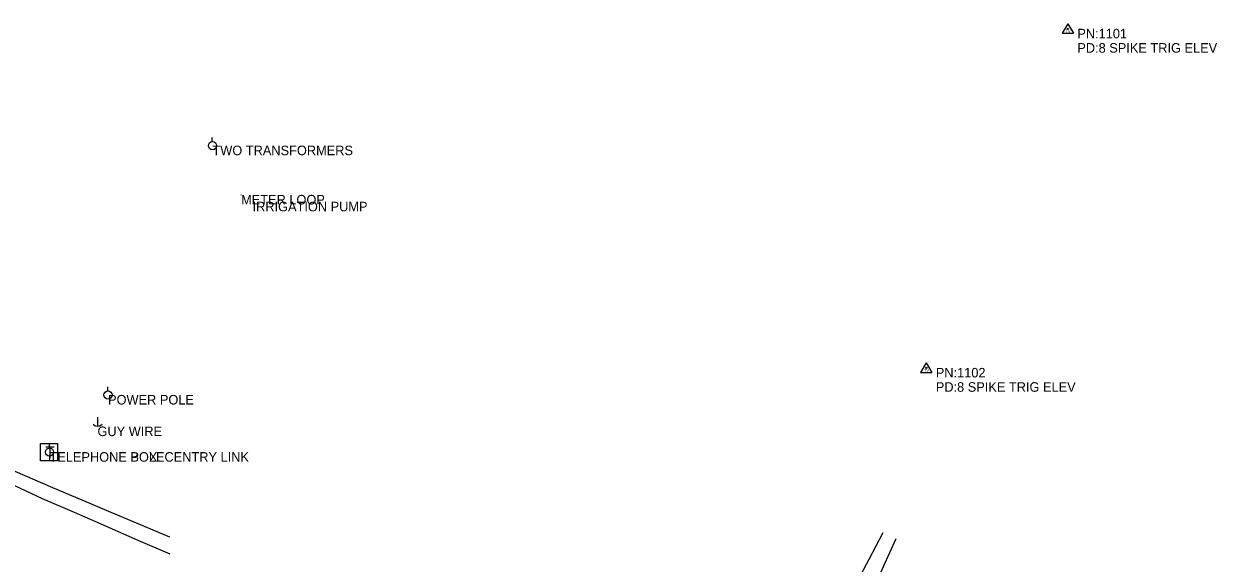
# Model space of a CAD drawing. Extents: x 1411444 to 1458157, y 300965 to 327300.
# Drawn here: x 1454655 to 1455280, y 302865 to 303147 of the extents above; entities that cross this region are included whole.
import ezdxf

# ---------------------------------------------------------------- set-up
doc = ezdxf.new("R2010")
doc.units = 0
for name, color, linetype in [('S_DITCHLINE', 7, 'Continuous'), ('S_GRAVEL_ROAD', 7, 'Continuous'), ('S_MISC_STRUCTURES_ANNOT', 7, 'Continuous'), ('S_MSC_PT_SYM', 7, 'Continuous'), ('S_SECONDARY_CTL', 7, 'Continuous'), ('S_SECONDARY_CTL_ANNOT', 7, 'Continuous'), ('S_TELEPHONE_UTILITIES', 7, 'Continuous'), ('S_TELEPHONE_UTILITIES_ANNOT', 7, 'Continuous'), ('S_UTILITY_POLE', 7, 'Continuous'), ('S_UTILITY_POLE_ANNOT', 7, 'Continuous')]:
    doc.layers.add(name, color=color, linetype=linetype)

msp = doc.modelspace()

# ---------------------------------------------------------------- linework, layer by layer
at = {"layer": 'S_DITCHLINE'}
for points in [[(1454731.72, 302869.5), (1454715.03, 302876.77), (1454698.33, 302884.04), (1454681.64, 302891.31), (1454664.94, 302898.58), (1454644.54, 302908.11), (1454624.14, 302917.64)], [(1454630.76, 302921.5), (1454650.43, 302913.01), (1454670.1, 302904.51), (1454685.4, 302898.04), (1454700.71, 302891.57), (1454716.01, 302885.1), (1454731.32, 302878.63)]]:
    msp.add_lwpolyline(points, dxfattribs=at)
at = {"layer": 'S_GRAVEL_ROAD'}
for points in [[(1455052.17, 302730.63), (1455054.14, 302746.92), (1455056.11, 302763.21), (1455060.56, 302781.24), (1455065.01, 302799.27), (1455071.31, 302812.73), (1455077.6, 302826.18), (1455083.9, 302839.64), (1455090.19, 302853.09), (1455097.56, 302866.95), (1455104.93, 302880.82)], [(1455060.51, 302728.6), (1455062.4, 302745.72), (1455064.29, 302762.85), (1455068.45, 302780.48), (1455072.61, 302798.11), (1455079.1, 302810.71), (1455085.59, 302823.31), (1455092.08, 302835.91), (1455098.57, 302848.52), (1455105.1, 302863.14), (1455111.62, 302877.76)]]:
    msp.add_lwpolyline(points, dxfattribs=at)
at = {"layer": 'S_MSC_PT_SYM'}
for points in [[(1454768.84, 303057.79), (1454768.84, 303057.84), (1454768.84, 303057.79), (1454768.79, 303057.79), (1454768.84, 303057.79), (1454768.84, 303057.74), (1454768.84, 303057.79), (1454768.89, 303057.79)], [(1454774.82, 303054.19), (1454774.82, 303054.24), (1454774.82, 303054.19), (1454774.77, 303054.19), (1454774.82, 303054.19), (1454774.82, 303054.14), (1454774.82, 303054.19), (1454774.87, 303054.19)]]:
    msp.add_lwpolyline(points, dxfattribs=at)
at = {"layer": 'S_SECONDARY_CTL'}
for p, q in [((1455201.5, 303147.44), (1455198.49, 303142.48)), ((1455198.49, 303142.48), (1455204.45, 303142.48)), ((1455201.5, 303147.44), (1455204.45, 303142.48)), ((1455127.43, 302969.76), (1455124.42, 302964.8)), ((1455127.43, 302969.76), (1455130.38, 302964.8)), ((1455124.42, 302964.8), (1455130.38, 302964.8))]:
    msp.add_line(p, q, dxfattribs=at)
for centre, radius in [((1455201.5, 303144.83), 0.311), ((1455201.5, 303144.83), 0.183), ((1455201.5, 303144.83), 0.103), ((1455127.43, 302967.15), 0.311), ((1455127.43, 302967.15), 0.183), ((1455127.43, 302967.15), 0.103)]:
    msp.add_circle(centre, radius, dxfattribs=at)
at = {"layer": 'S_TELEPHONE_UTILITIES'}
for p, q in [((1454668.52, 302925.09), (1454668.52, 302927.22)), ((1454668.52, 302920.87), (1454668.52, 302918.81))]:
    msp.add_line(p, q, dxfattribs=at)
msp.add_lwpolyline([(1454663.82, 302918.49), (1454663.82, 302927.49), (1454672.82, 302927.49), (1454672.82, 302918.49)], close=True, dxfattribs=at)
msp.add_circle((1454668.54, 302923.01), 2.11, dxfattribs=at)
at = {"layer": 'S_UTILITY_POLE'}
for p, q in [((1454753.72, 303085.75), (1454753.72, 303087.86)), ((1454699.07, 302955.11), (1454699.07, 302957.21)), ((1454693.66, 302941.35), (1454693.66, 302936.63))]:
    msp.add_line(p, q, dxfattribs=at)
for centre in [(1454753.84, 303083.61), (1454699.19, 302952.97)]:
    msp.add_circle(centre, 2.13, dxfattribs=at)
msp.add_arc((1454693.72, 302940.05), 3.41, 226.39718, 313.60282, dxfattribs=at)

# ---------------------------------------------------------------- texts
at = {"layer": 'S_MISC_STRUCTURES_ANNOT'}
for s, p in [('METER LOOP', (1454768.84, 303052.79)), ('IRRIGATION PUMP', (1454774.82, 303049.19))]:
    msp.add_text(s, height=5, dxfattribs=at).set_placement(p)
at = {"layer": 'S_SECONDARY_CTL'}
for p in [(1455200.3, 303142.82), (1455126.22, 302965.13)]:
    msp.add_text('TV', height=1.5, rotation=360, dxfattribs=at).set_placement(p)
at = {"layer": 'S_SECONDARY_CTL_ANNOT'}
for s, p in [('PN:1101', (1455206.5, 303139.83)), ('PD:8 SPIKE TRIG ELEV', (1455206.5, 303132.33)), ('PN:1102', (1455132.43, 302962.15)), ('PD:8 SPIKE TRIG ELEV', (1455132.43, 302954.65))]:
    msp.add_text(s, height=5, dxfattribs=at).set_placement(p)
at = {"layer": 'S_TELEPHONE_UTILITIES'}
msp.add_text('T', height=6, rotation=360, dxfattribs=at).set_placement((1454666.38, 302919.99))
at = {"layer": 'S_TELEPHONE_UTILITIES_ANNOT'}
for s in ['TELEPHONE POLE', 'TELEPHONE BOX. CENTRY LINK']:
    msp.add_text(s, height=5, dxfattribs=at).set_placement((1454668.54, 302918.01))
at = {"layer": 'S_UTILITY_POLE_ANNOT'}
for s, p in [('TWO TRANSFORMERS', (1454753.84, 303078.61)), ('POWER POLE', (1454699.19, 302947.97)), ('GUY WIRE', (1454693.67, 302931.41))]:
    msp.add_text(s, height=5, dxfattribs=at).set_placement(p)

doc.saveas('drawing.dxf')
